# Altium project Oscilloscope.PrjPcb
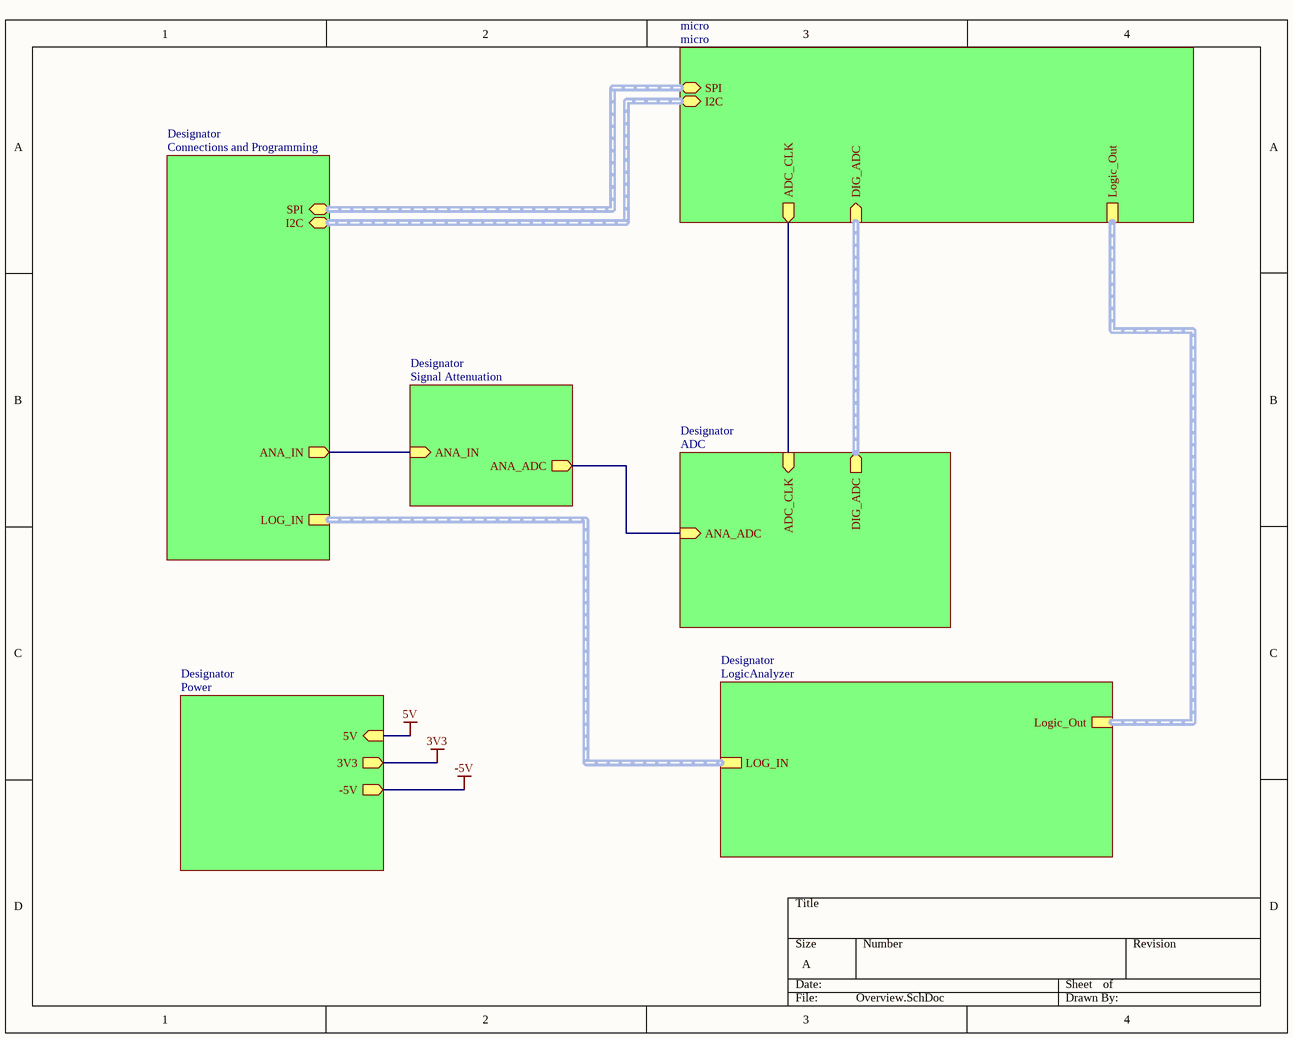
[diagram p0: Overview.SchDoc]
7 sheets, 84 parts. Net scope: hierarchical (ports join the sheet entries above them; power ports are global).
Board file: Oscilloscope.PcbDoc
Sheets:
  Overview.SchDoc
    Designator = Connections and Programming.SchDoc
    micro = micro.SchDoc
    Designator = ADC.SchDoc
    Designator = LogicAnalyzer.SchDoc
    Designator = Power.SchDoc
    Designator = Signal Attenuation.SchDoc

## Sheet Overview.SchDoc
size A

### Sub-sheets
Designator = Connections and Programming: ANA_IN (out), SPI (bidir), I2C (bidir), LOG_IN
Designator = ADC: ADC_CLK (in), DIG_ADC (out), ANA_ADC (in)
Designator = LogicAnalyzer: Logic_Out, LOG_IN
Designator = Power: 5V (in), 3V3 (out), -5V (out)
Designator = Signal Attenuation: ANA_IN (in), ANA_ADC (out)
micro = micro: ADC_CLK (out), DIG_ADC (in), Logic_Out, SPI (bidir), I2C (bidir)

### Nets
ADC_CLK: sheet micro/ADC_CLK, sheet Designator/ADC_CLK
ANA_IN: sheet Designator/ANA_IN, sheet Designator/ANA_IN
ANA_IN_HIGH: sheet Designator/ANA_ADC, sheet Designator/ANA_ADC

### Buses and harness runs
harness sheet Designator/DIG_ADC = sheet micro/DIG_ADC
harness sheet Designator/I2C = sheet micro/I2C
harness sheet Designator/Logic_Out = sheet micro/Logic_Out
harness sheet Designator/SPI = sheet micro/SPI

## Sheet Connections and Programming.SchDoc
size A
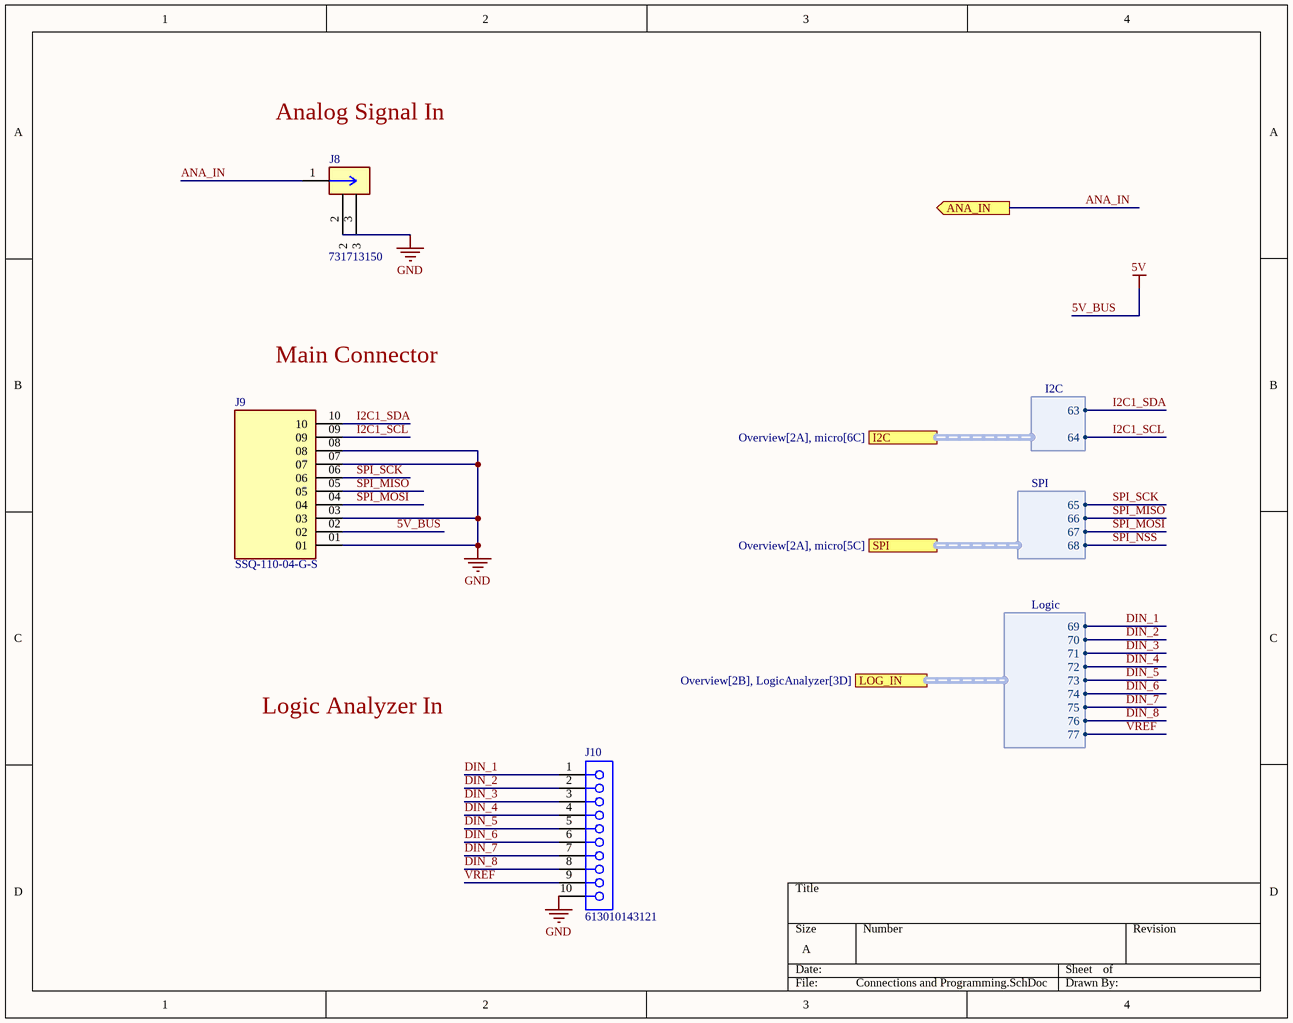
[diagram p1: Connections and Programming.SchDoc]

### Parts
J8  731713150  [CONN_731713150_MOL]
J9  SSQ-110-04-G-S  [SAMTEC_SSQ-110-04-G-S]
J10  613010143121  [613010143121]

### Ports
ANA_IN (out, see Overview[2B], Signal Attenuation[5C]), I2C (harness I2C, see Overview[2A], micro[6C]), LOG_IN (harness Logic, see Overview[2B], LogicAnalyzer[3D]), SPI (harness SPI, see Overview[2A], micro[5C])

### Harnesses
I2C: 63, 64
SPI: 65, 66, 67, 68
Logic: 69, 70, 71, 72, 73, 74, 75, 76, 77

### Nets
5V_BUS: J9.02  [also labelled 5V]
GND: J9.01 J9.03 J9.07 J9.08 J10.10
ANA_IN: J8.1 ; port ANA_IN
DIN_1: J10.1 ; port LOG_IN.69
DIN_2: J10.2 ; port LOG_IN.70
DIN_3: J10.3 ; port LOG_IN.71
DIN_4: J10.4 ; port LOG_IN.72
DIN_5: J10.5 ; port LOG_IN.73
DIN_6: J10.6 ; port LOG_IN.74
DIN_7: J10.7 ; port LOG_IN.75
DIN_8: J10.8 ; port LOG_IN.76
I2C1_SCL: J9.09 ; port I2C.64
I2C1_SDA: J9.10 ; port I2C.63
SPI_MISO: J9.05 ; port SPI.66
SPI_MOSI: J9.04 ; port SPI.67
SPI_SCK: J9.06 ; port SPI.65
VREF: J10.9 ; port LOG_IN.77

Not connected (* = marked no-connect by the designer): J8 2 3

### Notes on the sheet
- Analog Signal In
- Main Connector
- Logic Analyzer In

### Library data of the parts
J8 = CMP-002-00084-4: JACK, BNC, 50OHM, R/A, THT; Connector Type: BNC Coaxial; Body Style: Right Angle J; MP: 73171-3150; MF: Molex
J9 = CMP-039-000000-3: Samtec Connector .1" pitch, long ahh pins
J10 = CMP-1502-01419-3: NexarPartId: 18818161; Operating Supply Voltage: 250V; Contact Resistance: 20mΩ; Gender: Female; Insulation Resistance: 1GΩ; Connector Type: Header, Socket; Insulation: Insulated; Current Rating: 3A; Number of Positions: 10; Pitch: 2.54mm

## Sheet micro.SchDoc
size B
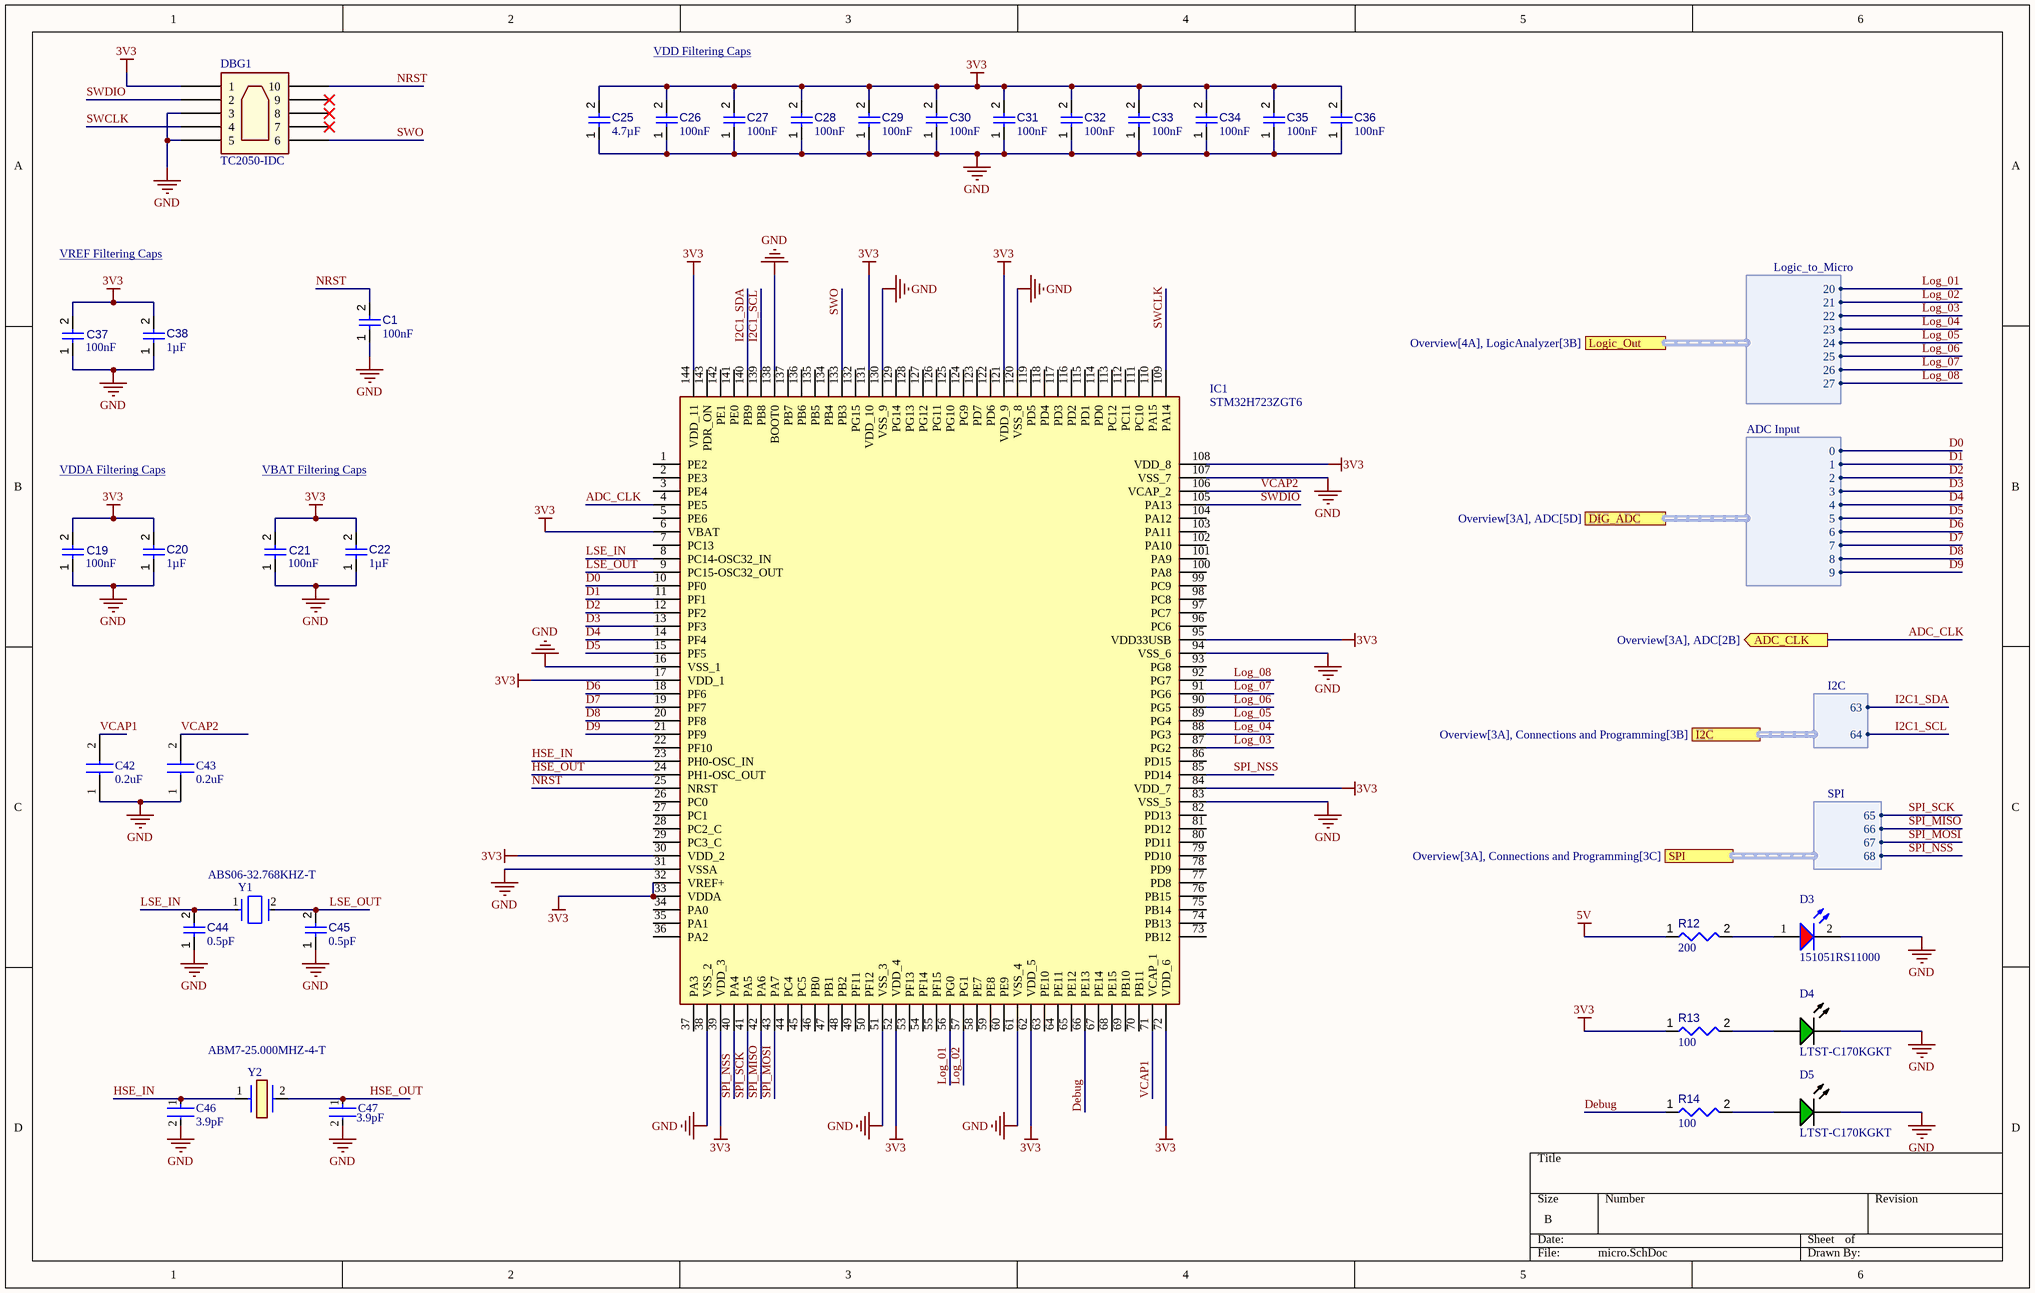
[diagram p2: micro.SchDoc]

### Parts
C1  value 100nF  [CAPC1005X56X25LL10T15]  (hidden comment: Capacitor 0.1 uF +/- 5% 16 V 0402)
C19  value 100nF  [CAPC0402(1005)60_L]  (hidden comment: Capacitor 100nF +/-20% 10V 0402)
C20  value 1µF  [CAPC1608X90X35ML15T15]  (hidden comment: Capacitor 1uF +/- 10% 16V 0603)
C21  value 100nF  [CAPC0402(1005)60_L]  (hidden comment: Capacitor 100nF +/-20% 10V 0402)
C22  value 1µF  [CAPC1608X90X35ML15T15]  (hidden comment: Capacitor 1uF +/- 10% 16V 0603)
C25  value 4.7µF  [CAPC0603(1608)100_L]  (hidden comment: Capacitor 4.7µF +/-20% 10V 0603)
C26  value 100nF  [CAPC0402(1005)60_L]  (hidden comment: Capacitor 100nF +/-20% 10V 0402)
C27  value 100nF  [CAPC0402(1005)60_L]  (hidden comment: Capacitor 100nF +/-20% 10V 0402)
C28  value 100nF  [CAPC0402(1005)60_L]  (hidden comment: Capacitor 100nF +/-20% 10V 0402)
C29  value 100nF  [CAPC0402(1005)60_L]  (hidden comment: Capacitor 100nF +/-20% 10V 0402)
C30  value 100nF  [CAPC0402(1005)60_L]  (hidden comment: Capacitor 100nF +/-20% 10V 0402)
C31  value 100nF  [CAPC0402(1005)60_L]  (hidden comment: Capacitor 100nF +/-20% 10V 0402)
C32  value 100nF  [CAPC0402(1005)60_L]  (hidden comment: Capacitor 100nF +/-20% 10V 0402)
C33  value 100nF  [CAPC0402(1005)60_L]  (hidden comment: Capacitor 100nF +/-20% 10V 0402)
C34  value 100nF  [CAPC0402(1005)60_L]  (hidden comment: Capacitor 100nF +/-20% 10V 0402)
C35  value 100nF  [CAPC0402(1005)60_L]  (hidden comment: Capacitor 100nF +/-20% 10V 0402)
C36  value 100nF  [CAPC0402(1005)60_L]  (hidden comment: Capacitor 100nF +/-20% 10V 0402)
C37  value 100nF  [CAPC0402(1005)60_L]  (hidden comment: Capacitor 100nF +/-20% 10V 0402)
C38  value 1µF  [CAPC1608X90X35ML15T15]  (hidden comment: Capacitor 1uF +/- 10% 16V 0603)
C42  0.2uF  [CAPC3216X94N]
C43  0.2uF  [CAPC3216X94N]
C44  value 0.5pF  [CAPC1005X56X25ML10T15]  (hidden comment: Capacitor 0.5 pF +/- 0.1pF 25 V 0402)
C45  value 0.5pF  [CAPC1005X56X25ML10T15]  (hidden comment: Capacitor 0.5 pF +/- 0.1pF 25 V 0402)
C46  3.9pF  [FP-GJM155-0_05-IPC_C]
C47  3.9pF  [FP-GJM155-0_05-IPC_C]
D3  151051RS11000  [WL-TMRC_D5.9H8.7]
D4  LTST-C170KGKT  [LTST-LTST-C170KGKT-2_V]
D5  LTST-C170KGKT  [LTST-LTST-C170KGKT-2_V]
DBG1  TC2050-IDC  [TC2050-IDC-Footprint-1]
IC1  STM32H723ZGT6  [QFP50P2200X2200X160-144N]
R12  value 200  [RESC0402(1005)_L]  (hidden comment: 200R2J)
R13  value 100  [RESC0402(1005)_L]  (hidden comment: 100R2F)
R14  value 100  [RESC0402(1005)_L]  (hidden comment: 100R2F)
Y1  ABS06-32.768KHZ-T  [FP-ABS06-MFG]
Y2  ABM7-25.000MHZ-4-T  [ABM7]

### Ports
ADC_CLK (out, see Overview[3A], ADC[2B]), DIG_ADC (harness ADC Input, see Overview[3A], ADC[5D]), I2C (harness I2C, see Overview[3A], Connections and Programming[3B]), Logic_Out (harness Logic_to_Micro, see Overview[4A], LogicAnalyzer[3B]), SPI (harness SPI, see Overview[3A], Connections and Programming[3C])

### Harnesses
ADC Input: 0, 1, 2, 3, 4, 5, 6, 7, 8, 9
Logic_to_Micro: 20, 21, 22, 23, 24, 25, 26, 27
I2C: 63, 64
SPI: 65, 66, 67, 68

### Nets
3V3: C19.2 C20.2 C21.2 C22.2 C25.2 C26.2 C27.2 C28.2 C29.2 C30.2 C31.2 C32.2 C33.2 C34.2 C35.2 C36.2 C37.2 C38.2 DBG1.1 IC1.6(VBAT) IC1.17(VDD_1) IC1.30(VDD_2) IC1.32(VREF+) IC1.33(VDDA) IC1.39(VDD_3) IC1.52(VDD_4) IC1.62(VDD_5) IC1.72(VDD_6) IC1.84(VDD_7) IC1.95(VDD33USB) IC1.108(VDD_8) IC1.121(VDD_9) IC1.131(VDD_10) IC1.144(VDD_11) R13.1
5V: R12.1  [project net 5V_BUS]
GND: C1.1 C19.1 C20.1 C21.1 C22.1 C25.1 C26.1 C27.1 C28.1 C29.1 C30.1 C31.1 C32.1 C33.1 C34.1 C35.1 C36.1 C37.1 C38.1 C42.1(C1) C43.1(C1) C44.1 C45.1 C46.2 C47.2 D3.2(K) D4.1(K) D5.1(K) DBG1.3 DBG1.5 IC1.16(VSS_1) IC1.31(VSSA) IC1.38(VSS_2) IC1.51(VSS_3) IC1.61(VSS_4) IC1.83(VSS_5) IC1.94(VSS_6) IC1.107(VSS_7) IC1.120(VSS_8) IC1.130(VSS_9) IC1.138(BOOT0)
ADC_CLK: IC1.4(PE5) ; port ADC_CLK
D0: IC1.10(PF0) ; port DIG_ADC.0
D1: IC1.11(PF1) ; port DIG_ADC.1
D2: IC1.12(PF2) ; port DIG_ADC.2
D3: IC1.13(PF3) ; port DIG_ADC.3
D4: IC1.14(PF4) ; port DIG_ADC.4
D5: IC1.15(PF5) ; port DIG_ADC.5
D6: IC1.18(PF6) ; port DIG_ADC.6
D7: IC1.19(PF7) ; port DIG_ADC.7
D8: IC1.20(PF8) ; port DIG_ADC.8
D9: IC1.21(PF9) ; port DIG_ADC.9
Debug: IC1.66(PE13) R14.1
HSE_IN: C46.1 IC1.23(PH0-OSC_IN) Y2.1
HSE_OUT: C47.1 IC1.24(PH1-OSC_OUT) Y2.2
I2C1_SCL: IC1.139(PB8) ; port I2C.64
I2C1_SDA: IC1.140(PB9) ; port I2C.63
Log_01: IC1.56(PG0) ; port Logic_Out.20
Log_02: IC1.57(PG1) ; port Logic_Out.21
Log_03: IC1.87(PG2) ; port Logic_Out.22
Log_04: IC1.88(PG3) ; port Logic_Out.23
Log_05: IC1.89(PG4) ; port Logic_Out.24
Log_06: IC1.90(PG5) ; port Logic_Out.25
Log_07: IC1.91(PG6) ; port Logic_Out.26
Log_08: IC1.92(PG7) ; port Logic_Out.27
LSE_IN: C44.2 IC1.8(PC14-OSC32_IN) Y1.1
LSE_OUT: C45.2 IC1.9(PC15-OSC32_OUT) Y1.2
NRST: C1.2 DBG1.10 IC1.25(NRST)
SPI_MISO: IC1.42(PA6) ; port SPI.66
SPI_MOSI: IC1.43(PA7) ; port SPI.67
SPI_NSS: IC1.40(PA4) IC1.85(PD14) ; port SPI.68
SPI_SCK: IC1.41(PA5) ; port SPI.65
SWCLK: DBG1.4 IC1.109(PA14)
SWDIO: DBG1.2 IC1.105(PA13)
SWO: DBG1.6 IC1.133(PB3)
VCAP1: C42.2(C2) IC1.71(VCAP_1)
VCAP2: C43.2(C2) IC1.106(VCAP_2)
NetD3_1: D3.1(A) R12.2
NetD4_2: D4.2(A) R13.2
NetD5_2: D5.2(A) R14.2

Not connected (* = marked no-connect by the designer): DBG1 7* 8* 9*; IC1 1(PE2) 2(PE3) 3(PE4) 5(PE6) 7(PC13) 22(PF10) 26(PC0) 27(PC1) 28(PC2_C) 29(PC3_C) 34(PA0) 35(PA1) 36(PA2) 37(PA3) 44(PC4) 45(PC5) 46(PB0) 47(PB1) 48(PB2) 49(PF11) 50(PF12) 53(PF13) 54(PF14) 55(PF15) 58(PE7) 59(PE8) 60(PE9) 63(PE10) 64(PE11) 65(PE12) 67(PE14) 68(PE15) 69(PB10) 70(PB11) 73(PB12) 74(PB13) 75(PB14) 76(PB15) 77(PD8) 78(PD9) 79(PD10) 80(PD11) 81(PD12) 82(PD13) 86(PD15) 93(PG8) 96(PC6) 97(PC7) 98(PC8) 99(PC9) 100(PA8) 101(PA9) 102(PA10) 103(PA11) 104(PA12) 110(PA15) 111(PC10) 112(PC11) 113(PC12) 114(PD0) 115(PD1) 116(PD2) 117(PD3) 118(PD4) 119(PD5) 122(PD6) 123(PD7) 124(PG9) 125(PG10) 126(PG11) 127(PG12) 128(PG13) 129(PG14) 132(PG15) 134(PB4) 135(PB5) 136(PB6) 137(PB7) 141(PE0) 142(PE1) 143(PDR_ON)

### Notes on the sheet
- VDD Filtering Caps
- VREF Filtering Caps
- VDDA Filtering Caps
- VBAT Filtering Caps

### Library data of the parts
C1 = CMP-001-00001-6: Chip Capacitor, 0.1 uF, +/- 5%, 16 V, 0402 (1005 Metric); Capacitor Type: Ceramic; Voltage Rating: 16V
C19 C21 C26-C37 = CMP-001-00061-3: Chip Capacitor, 100nF +/-20%, 10V, 0402, Thickness 0.6 mm; Tolerance: 20%
C20 C22 C38 = CMP-001-00004-6: Chip Capacitor, 1 uF, +/- 10%, 16 V, 0603 (1608 Metric); Capacitor Type: Ceramic
C25 = CMP-001-00076-4: Chip Capacitor, 4.7µF +/-20%, 10V, 0603, Thickness 1 mm; Tolerance: 10%
C42 C43 = 12063C204KAT4A: Capacitor; Manufacturer_Name: Kyocera AVX
C44 C45 = CMP-001-00002-6: Chip Capacitor, 0.5 pF, +/- 0.1pF, 25 V, 0402 (1005 Metric); Voltage Rating: 25V; Tolerance: 20%; Capacitor Type: Ceramic
C46 C47 = CMP-2008-03853-2: Multi-Layer Ceramic Capacitor 3.9pF C0G  ±0.25pF 0402 Paper T/R; Voltage Rating (DC): 50V
D3 = CMP-007-00039-1: WL-TMRC Red Color Diffused 5 mm Round Through Hole LED; Forward Voltage: 2.1V; Forward Current: 100mA
D4 D5 = CMP-2000-06620-1: Ultra Bright AlInGaP Chip LED, 75 mW, -55 to 85 degC, 2-Pin SMD (0805), RoHS, Tape and Reel; Manufacturer: Lite-On; Forward Current: 30mA; Power Dissipation Max: 75mW; Emitting Color: YellowGreen; Type: Uni-Color; Forward Voltage: 2.4V; Dominant Wave Length: 571nm; Test Current (It): 20mA; Product Length (mm): 2mm; Peak Wavelength: 574nm; Power Dissipation: 75W; Product Depth (mm): 1.25mm; DELETED: Compliant; High Brightness: Yes; Product Height (mm): 1.1mm; Luminous Intensity: 35mcd; Shape Type: Rectangular; Chip Material: AlGaInP; Viewing Angle: 130deg; Number of  Elements: 1; Reverse Voltage: 5V; Rad Hardened: No
DBG1 = CMP-002-00071-4: CBL PLUG-OF-NAILS 10-PIN W/LEGS
IC1 = STM32H723ZGT6: Integrated Circuit; Manufacturer_Name: STMicroelectronics
R12 = CMP-009-00079-2: 200R 0.063W 5% 0402 (1005 Metric)  SMD; Power: 63mW
R13 R14 = CMP-009-00065-2: 100R 0.063W 1% 0402 (1005 Metric)  SMD; Power: 63mW
Y1 = CMP-2000-05035-2: Crystal 32.768kHz ±20ppm (Tol) 12.5pF FUND 90kΩ 2-Pin Mini-CSMD T/R; Insulation Resistance: 500MR; ESR (Equivalent Series Resistance): 90kR
Y2 = ABM7-25.000MHZ-4-T: Crystal or Oscillator; Manufacturer_Name: ABRACON

## Sheet ADC.SchDoc
size B
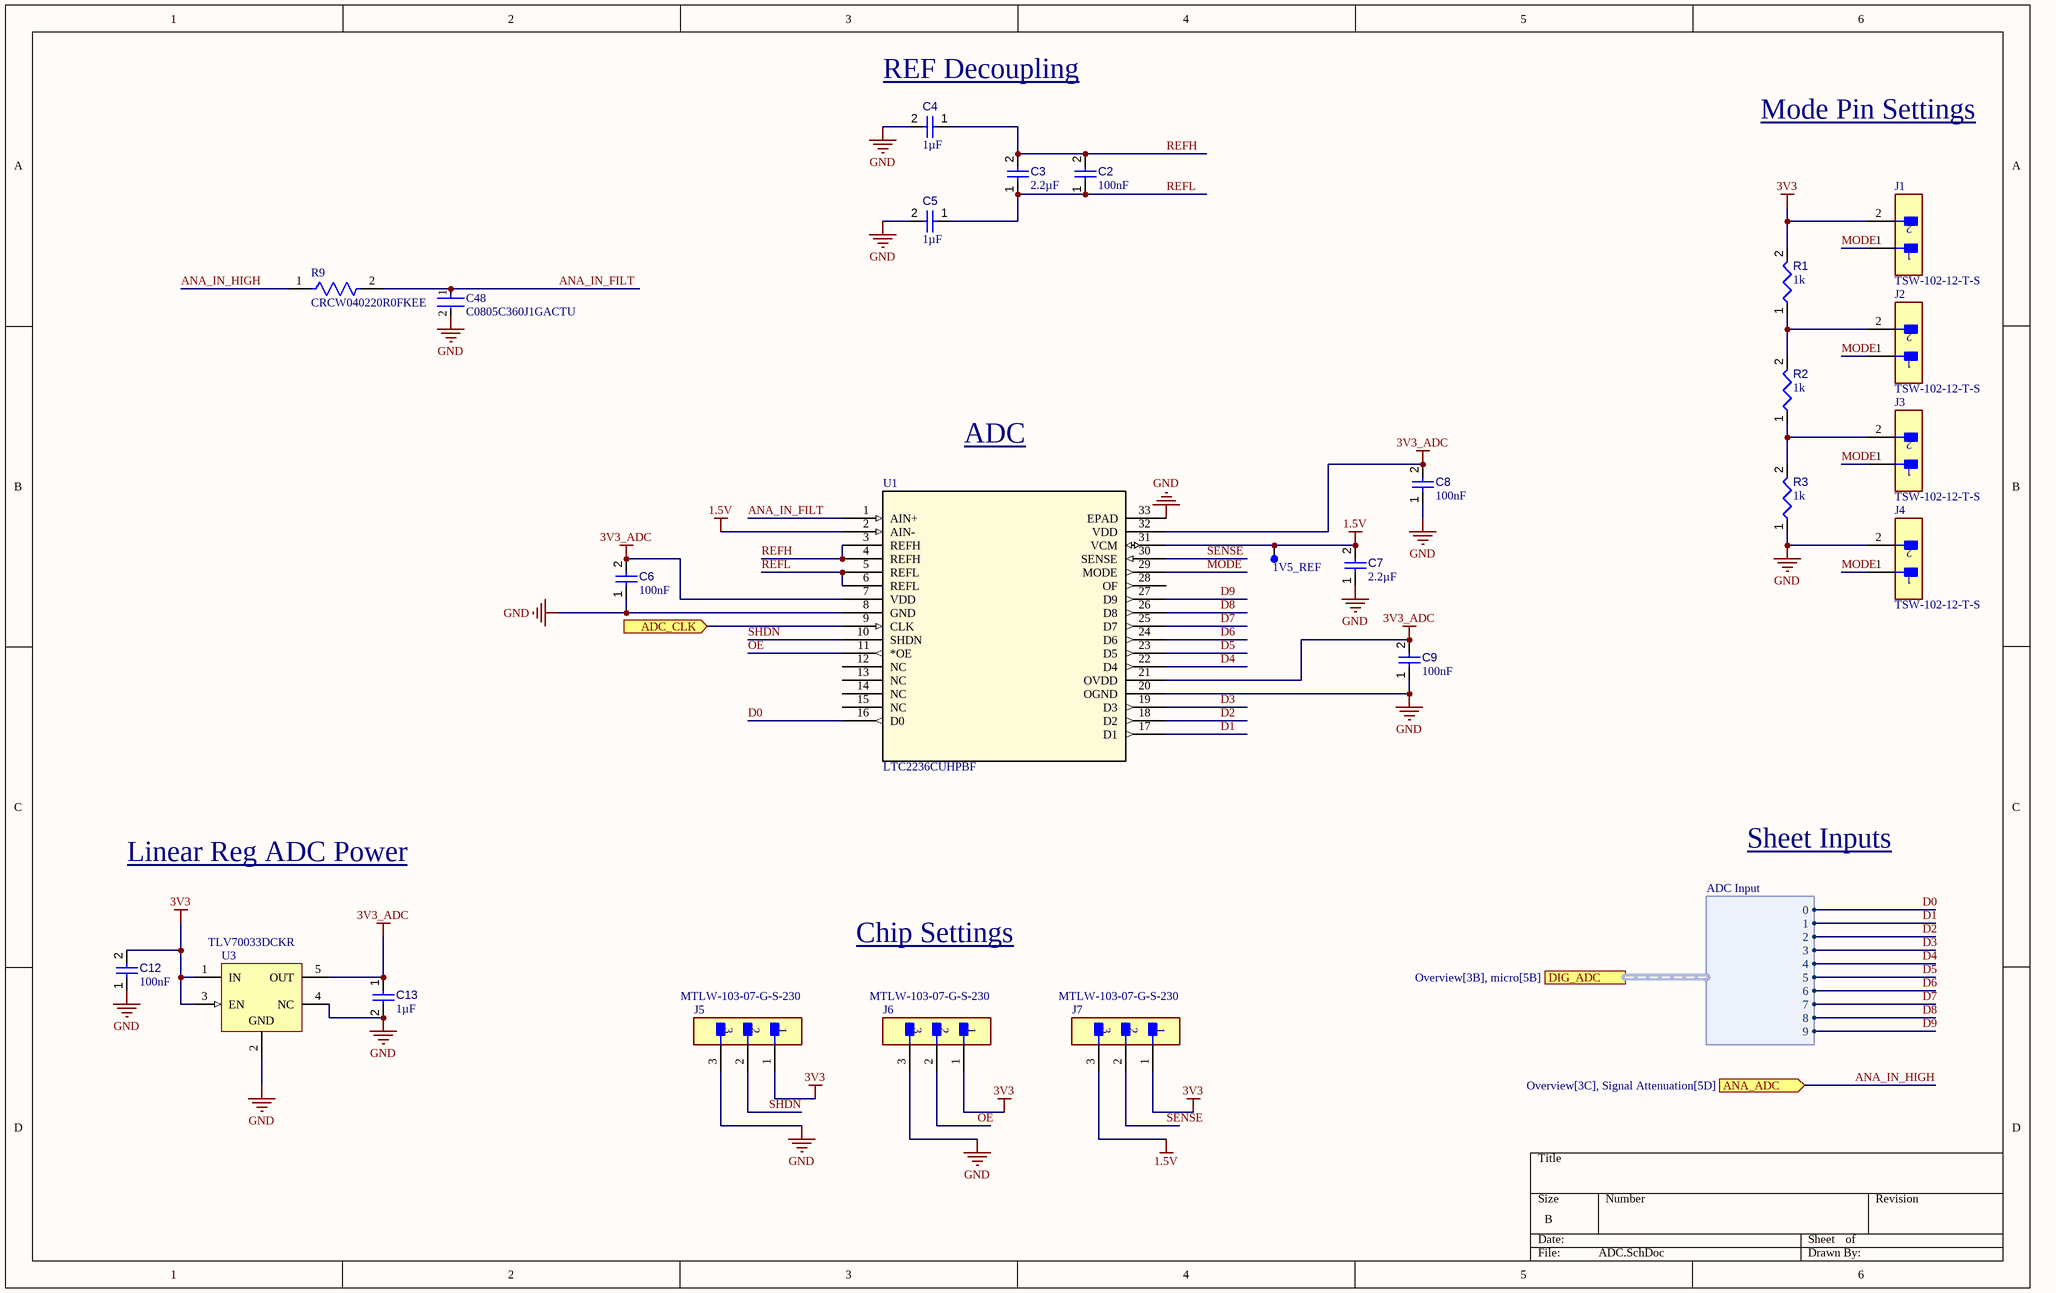
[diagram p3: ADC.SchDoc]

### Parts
1V5_REF  TESTPAD  [TESTPAD-Footprint-1]  (value not drawn)
C2  value 100nF  [CAPC1005X56X25LL10T15]  (hidden comment: Capacitor 0.1 uF +/- 5% 16 V 0402)
C3  value 2.2µF  [CAPC0402(1005)60_L]  (hidden comment: Capacitor 2,2µF +/-20% 10V 0402)
C4  value 1µF  [CAPC0402(1005)60_L]  (hidden comment: Capacitor 1µF +/-20% 10V 0402)
C5  value 1µF  [CAPC0402(1005)60_L]  (hidden comment: Capacitor 1µF +/-20% 10V 0402)
C6  value 100nF  [CAPC1005X56X25LL10T15]  (hidden comment: Capacitor 0.1 uF +/- 5% 16 V 0402)
C7  value 2.2µF  [CAPC0402(1005)60_L]  (hidden comment: Capacitor 2,2µF +/-20% 10V 0402)
C8  value 100nF  [CAPC1005X56X25LL10T15]  (hidden comment: Capacitor 0.1 uF +/- 5% 16 V 0402)
C9  value 100nF  [CAPC1005X56X25LL10T15]  (hidden comment: Capacitor 0.1 uF +/- 5% 16 V 0402)
C12  value 100nF  [CAPC1005X56X25LL10T15]  (hidden comment: Capacitor 0.1 uF +/- 5% 16 V 0402)
C13  value 1µF  [CAPC0402(1005)60_L]  (hidden comment: Capacitor 1µF +/-20% 10V 0402)
C48  C0805C360J1GACTU  [FP-C0805C-DN-MFG]
J1  TSW-102-12-T-S  [FP-TSW-102-12-T-S-MFG]
J2  TSW-102-12-T-S  [FP-TSW-102-12-T-S-MFG]
J3  TSW-102-12-T-S  [FP-TSW-102-12-T-S-MFG]
J4  TSW-102-12-T-S  [FP-TSW-102-12-T-S-MFG]
J5  MTLW-103-07-G-S-230  [FP-MTLW-103-07-G-S-230-MFG]
J6  MTLW-103-07-G-S-230  [FP-MTLW-103-07-G-S-230-MFG]
J7  MTLW-103-07-G-S-230  [FP-MTLW-103-07-G-S-230-MFG]
R1  value 1k  [RESC1608X55X25ML10T15]  (hidden comment: Resistor 1k +/-1% 0603 100 mW)
R2  value 1k  [RESC1608X55X25ML10T15]  (hidden comment: Resistor 1k +/-1% 0603 100 mW)
R3  value 1k  [RESC1608X55X25ML10T15]  (hidden comment: Resistor 1k +/-1% 0603 100 mW)
R9  CRCW040220R0FKEE  [FP-CRCW0402-e3-IPC_C]
U1  LTC2236CUHPBF  [QFN-32_UH_LIT]
U3  TLV70033DCKR  [DCK0005A_M]

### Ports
ADC_CLK (in, see Overview[3B], micro[6B]), ANA_ADC (in, see Overview[3C], Signal Attenuation[5D]), DIG_ADC (harness ADC Input, see Overview[3B], micro[5B])

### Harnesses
ADC Input: 0, 1, 2, 3, 4, 5, 6, 7, 8, 9

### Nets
1.5V: 1V5_REF.PAD C7.2 J7.3 U1.2(AIN-) U1.31(VCM)
3V3: C12.2 J1.2 J5.1 J6.1 J7.1 R1.2 U3.1(IN) U3.3(EN)
3V3_ADC: C6.2 C8.2 C9.2 C13.1 U1.7(VDD) U1.21(OVDD) U1.32(VDD) U3.5(OUT)
GND: C4.2 C5.2 C6.1 C7.1 C8.1 C9.1 C12.1 C13.2 C48.2 J4.2 J5.3 J6.3 R3.1 U1.8(GND) U1.20(OGND) U1.33(EPAD) U3.2(GND) U3.4(NC)
ADC_CLK: U1.9(CLK) ; port ADC_CLK
ANA_IN_FILT: C48.1 R9.2 U1.1(AIN+)
ANA_IN_HIGH: R9.1 ; port ANA_ADC
D0: U1.16(D0) ; port DIG_ADC.0
D1: U1.17(D1) ; port DIG_ADC.1
D2: U1.18(D2) ; port DIG_ADC.2
D3: U1.19(D3) ; port DIG_ADC.3
D4: U1.22(D4) ; port DIG_ADC.4
D5: U1.23(D5) ; port DIG_ADC.5
D6: U1.24(D6) ; port DIG_ADC.6
D7: U1.25(D7) ; port DIG_ADC.7
D8: U1.26(D8) ; port DIG_ADC.8
D9: U1.27(D9) ; port DIG_ADC.9
MODE: J1.1 J2.1 J3.1 J4.1 U1.29(MODE)
OE: J6.2 U1.11(*OE)
REFH: C2.2 C3.2 C4.1 U1.3(REFH) U1.4(REFH)
REFL: C2.1 C3.1 C5.1 U1.5(REFL) U1.6(REFL)
SENSE: J7.2 U1.30(SENSE)
SHDN: J5.2 U1.10(SHDN)
NetJ2_2: J2.2 R1.1 R2.2
NetJ3_2: J3.2 R2.1 R3.2

Not connected (* = marked no-connect by the designer): U1 12(NC) 13(NC) 14(NC) 15(NC) 28(OF)

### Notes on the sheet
- (near C4) REF Decoupling
- Mode Pin Settings
- ADC
- Linear Reg ADC Power
- Sheet Inputs
- Chip Settings

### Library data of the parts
1V5_REF = CMP-002-00073-1: PCB TESTPAD
C2 C6 C8 C9 C12 = CMP-001-00001-6: as C1 on sheet micro
C3 C7 = CMP-001-00056-4: Chip Capacitor, 2,2µF +/-20%, 10V, 0402, Thickness 0.6 mm; Tolerance: 10%
C4 C5 C13 = CMP-001-00063-3: Chip Capacitor, 1µF +/-20%, 10V, 0402, Thickness 0.6 mm; Tolerance: 10%
C48 = CMP-1036-01479-3: Capacitor, Ceramic, 36pF, 100VDC, 5-% Tol, 5+% Tol, C0G-TC Code, -30, 30ppm-TC; Manufacturer: KEMET; Temperature Characteristic: C0G; Description: C0805 36 pF C0G 30ppm/°C 5.00% 100 V; Tolerance: 0.05; Voltage Rating: 100 V; Temperature Coefficient: 30ppm/°C
J1-J4 = CMP-02766-001444-1: CONN HEADER VERT 2POS 2.54MM; Gender: Male; Number of Contacts: 2
J5-J7 = CMP-02766-001679-1: CONN HEADER VERT 3POS 2.54MM; Max Current Rating: 3A; Number of Contacts: 3; Gender: Male
R1-R3 = CMP-009-00014-5: Chip Resistor, 1 KOhm, +/-1%, 0.1 W, -55 to 155 degC, 0603 (1608 Metric); Voltage Rating: 50V; Power: 100mW; Tolerance: 1%
R9 = CMP-02407-010876-1: RES Thick Film, 20Ω, 1%, 0.063W, 100ppm/°C, 0402; Max Power Dissipation: 63mW; Resistance: 20R
U1 = CMP-027-000001-1: 10-Bit, 25Msps Low Noise 3V ADCs; Manufacturer_Name: Analog Devices Inc; Manufacturer_Part_Number: LTC2236CUH#PBF
U3 = CMP-0394-00820-2: Single Output LDO, 200 mA, Fixed 3.3 V Output, 2 to 5.5 V Input, with Low IQ, 5-pin SC70 (DCK), -40 to 125 degC, Green (RoHS & no Sb/Br); Manufacturer: Texas Instruments; SubFamily: Single Channel LDO; Fixed Output Options(V): 3.3; Vin(Max)(V): 5.5; Vin(Min)(V): 2; Vdo(Typ)(mV): 175; Iq(Typ)(mA): 0.03; Iout(Max)(A): 0.2

## Sheet LogicAnalyzer.SchDoc
size B
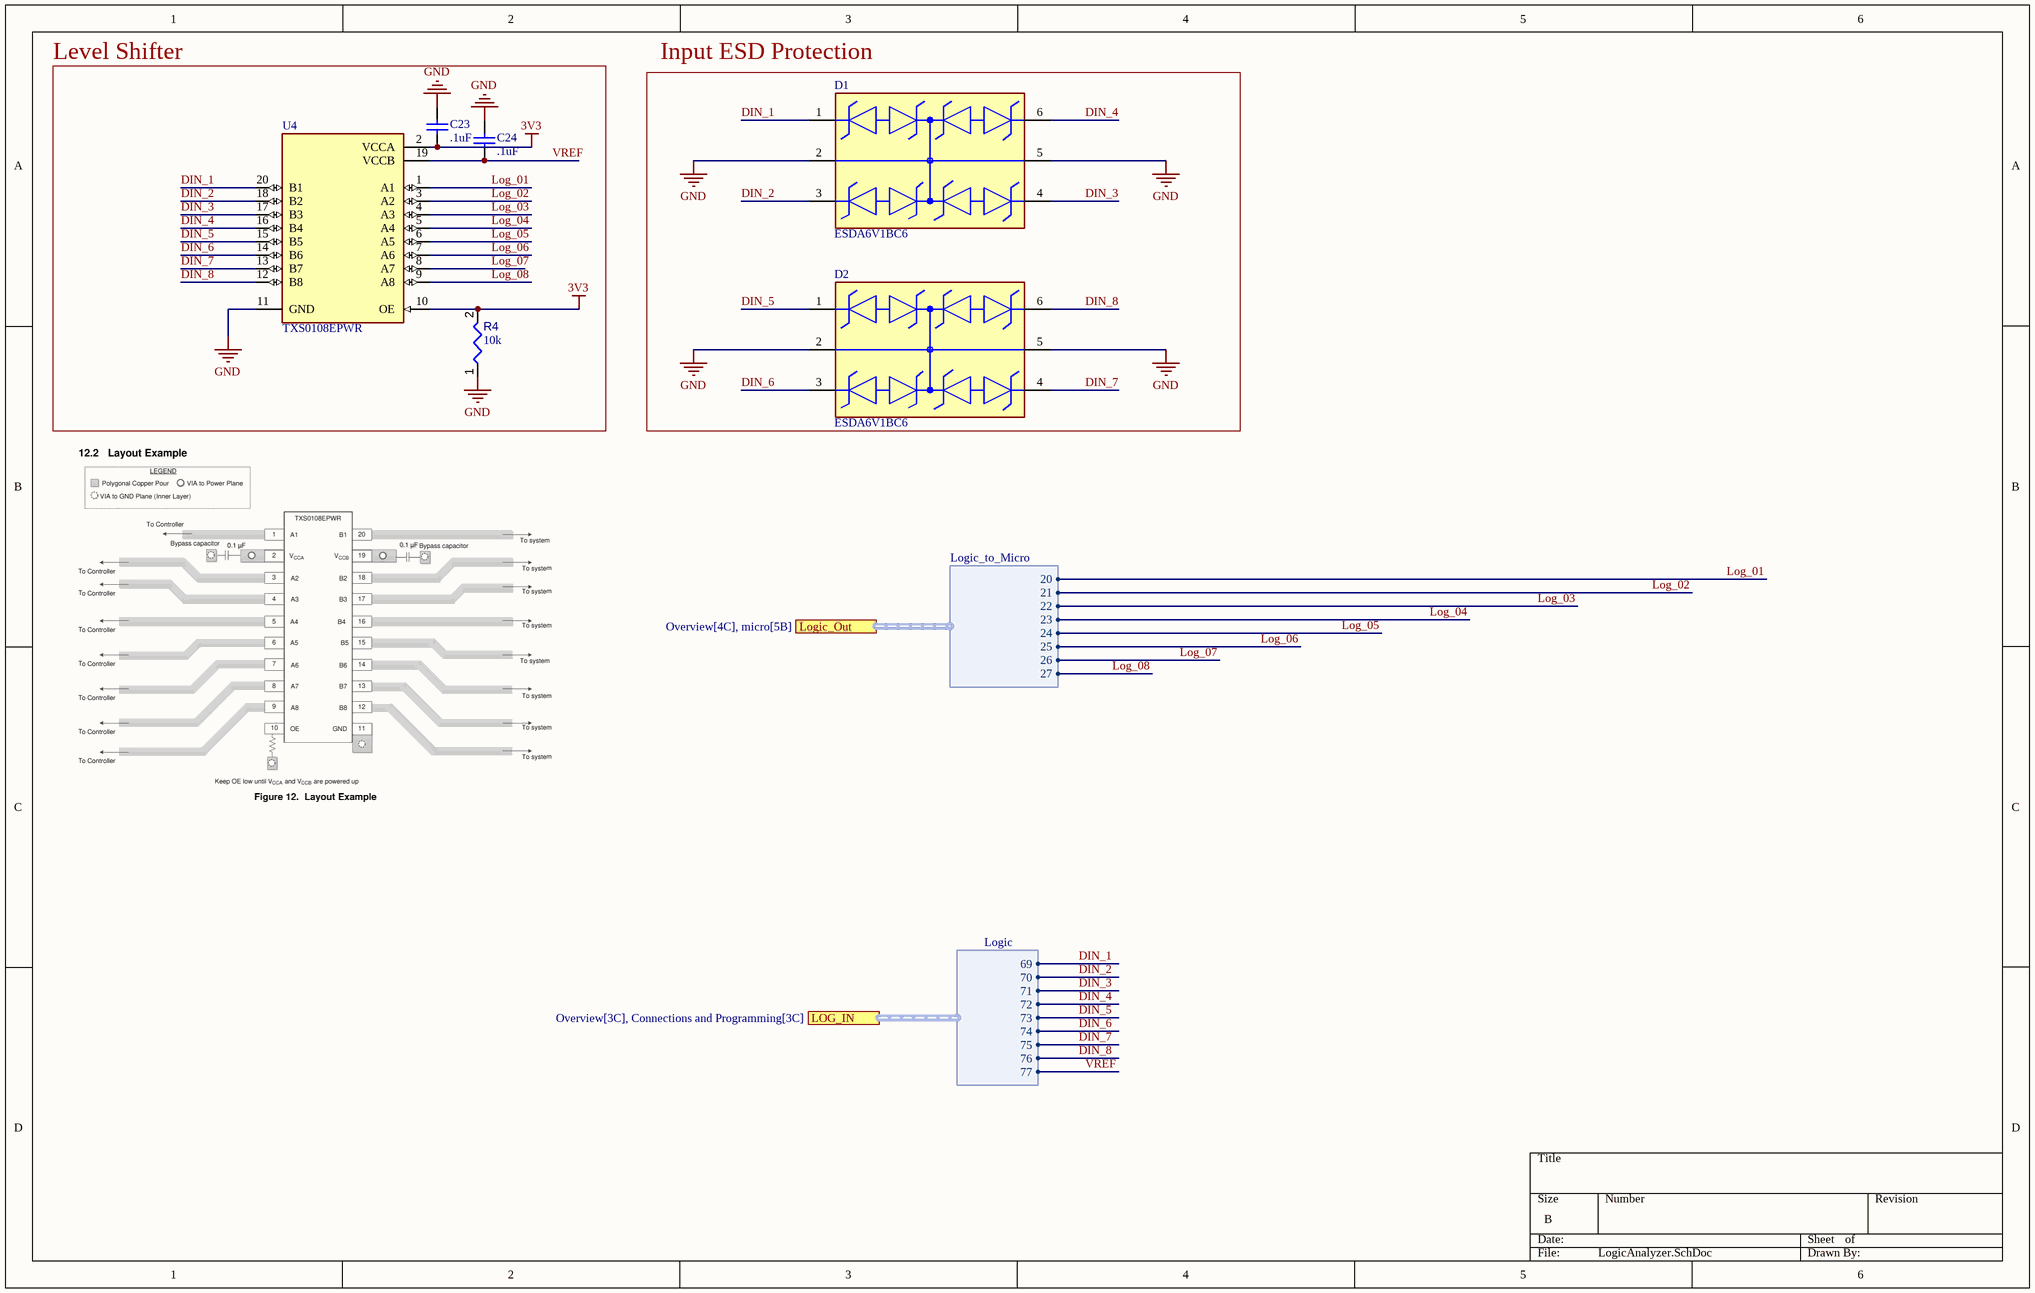
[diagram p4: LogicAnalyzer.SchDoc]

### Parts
C23  .1uF  [CAPC1608X90X35NL15T15]
C24  .1uF  [CAPC1608X90X35NL15T15]
D1  ESDA6V1BC6  [FP-SOT23-6L-MFG]
D2  ESDA6V1BC6  [FP-SOT23-6L-MFG]
R4  value 10k  [RESC0402(1005)_L]  (hidden comment: Resistor 10K  +/-1 % 0402 63 mW)
U4  TXS0108EPWR  [FP-PW0020A-IPC_A]

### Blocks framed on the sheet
Level Shifter: C23 C24 R4 U4
Input ESD Protection: D1 D2

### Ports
LOG_IN (harness Logic, see Overview[3C], Connections and Programming[3C]), Logic_Out (harness Logic_to_Micro, see Overview[4C], micro[5B])

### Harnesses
Logic_to_Micro: 20, 21, 22, 23, 24, 25, 26, 27
Logic: 69, 70, 71, 72, 73, 74, 75, 76, 77

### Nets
3V3: C23.2 R4.2 U4.2(VCCA) U4.10(OE)
GND: C23.1 C24.1 D1.2 D1.5 D2.2 D2.5 R4.1 U4.11(GND)
DIN_1: D1.1 U4.20(B1) ; port LOG_IN.69
DIN_2: D1.3 U4.18(B2) ; port LOG_IN.70
DIN_3: D1.4 U4.17(B3) ; port LOG_IN.71
DIN_4: D1.6 U4.16(B4) ; port LOG_IN.72
DIN_5: D2.1 U4.15(B5) ; port LOG_IN.73
DIN_6: D2.3 U4.14(B6) ; port LOG_IN.74
DIN_7: D2.4 U4.13(B7) ; port LOG_IN.75
DIN_8: D2.6 U4.12(B8) ; port LOG_IN.76
Log_01: U4.1(A1) ; port Logic_Out.20
Log_02: U4.3(A2) ; port Logic_Out.21
Log_03: U4.4(A3) ; port Logic_Out.22
Log_04: U4.5(A4) ; port Logic_Out.23
Log_05: U4.6(A5) ; port Logic_Out.24
Log_06: U4.7(A6) ; port Logic_Out.25
Log_07: U4.8(A7) ; port Logic_Out.26
Log_08: U4.9(A8) ; port Logic_Out.27
VREF: C24.2 U4.19(VCCB) ; port LOG_IN.77

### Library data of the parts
C23 C24 = CMP-2006-02299-1: C0603C104K4RAC7013; Manufacturer: Kemet
D1 D2 = CMP-12225-000005-1: TVS DIODE 5V SOT23-6; Manufacturer: STMicroelectronics; Direction: Bidirectional; Capacitance: 20pF; Standoff Height: 0mm; Number Of Channels: 4; Peak Pulse Power: 80W; Max Junction Temp: +150°C; Breakdown Voltage: 6.1V; Peak Pulse Current: 3A; Value: 20pF
R4 = CMP-009-00149-3: Chip Resistor, 10 kOhms, +/-1 %, 63 mW, -55 to 125 degC, 0402; Power: 63mW; Tolerance: 1%
U4 = CMP-016-00012-1: Eight-bit bidirectional voltage-level shifter for open-drain and push-pull applications 20-TSSOP -40 to 85; Min Supply Voltage: 1.4V; Nominal Supply Current: 3µA; Max Supply Voltage: 5.5V

## Sheet Power.SchDoc
size A
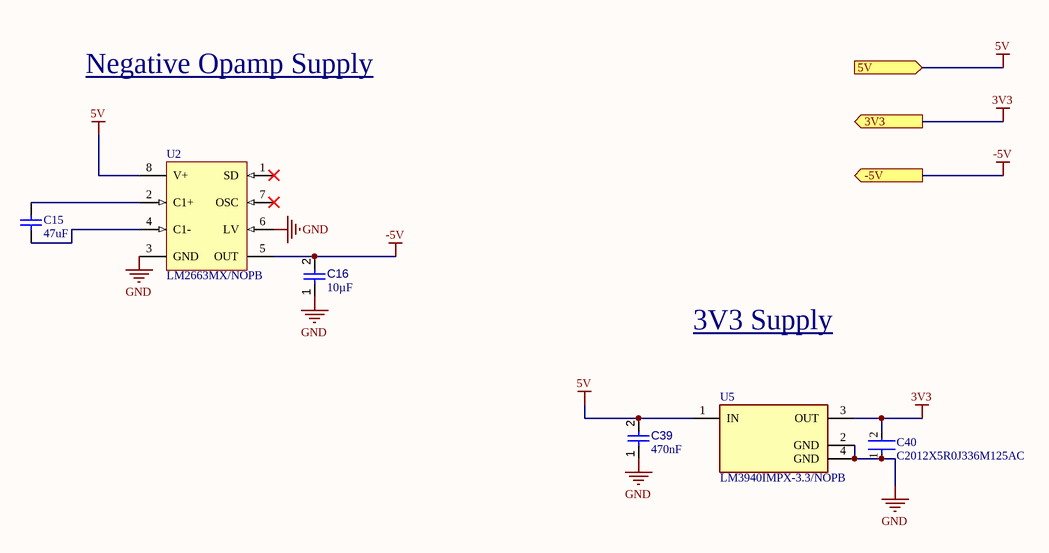
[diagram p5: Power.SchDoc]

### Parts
C15  47uF  [CAPC1206(3216)190_N]
C16  value 10µF  [CAPC0603(1608)100_L]  (hidden comment: Capacitor 10µF +/-20% 10V 0603)
C39  value 470nF  [CAPC0402(1005)60_L]  (hidden comment: Capacitor 470nF +/-40% 10V 0402)
C40  C2012X5R0J336M125AC  [FP-C2012-125-0_2-IPC_A]
U2  LM2663MX/NOPB  [D0008A_M]
U5  LM3940IMPX-3.3/NOPB  [FP-DCY0004A-MFG]

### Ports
3V3 (out), 5V (in), -5V (out)

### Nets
3V3: C40.2 U5.3(OUT) ; port 3V3
5V: C39.2 U2.8(V+) U5.1(IN) ; port 5V  [project net 5V_BUS]
-5V: C16.2 U2.5(OUT) ; port -5V
GND: C16.1 C39.1 C40.1 U2.3(GND) U2.6(LV) U5.2(GND) U5.4(GND)
NetC15_1: C15.1 U2.4(C1-)
NetC15_2: C15.2 U2.2(C1+)

Not connected (* = marked no-connect by the designer): U2 1(SD)* 7(OSC)*

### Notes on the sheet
- Negative Opamp Supply
- 3V3 Supply

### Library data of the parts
C15 = CMP-1037-05002-1: CAP 47uF 10V ±20% 1206 (3216 Metric) Thickness 1.9mm SMD; Case-Metric: 3216; Case-EIA: 1206; Tolerance: Â±20%
C16 = CMP-001-00075-4: Chip Capacitor, 10µF +/-20%, 10V, 0603, Thickness 1 mm; Tolerance: 10%
C39 = CMP-001-00060-4: Chip Capacitor, 470nF +/-40%, 10V, 0402, Thickness 0.6 mm; Tolerance: 20%
C40 = CMP-08246-003796-1: Multilayer Ceramic Capacitors 33μF ±20% 6.3V X5R SMD 0805; Capacitance: 33uF
U2 = CMP-0065-00039-3: Switched Capacitor Voltage Converter, 8-pin Narrow SOIC, Pb-Free; Manufacturer: Texas Instruments; PowerWise: N; PackageTopMarking: NSZXTT*LM26*63M; CompType: Switch Caps
U5 = CMP-04917-000180-1: IC REG LINEAR 3.3V 1A SOT223-4; Polarity: Positive; Dropout Voltage: 500mV; Number of Regulators: 1; Min Input Voltage: 4.5V; Quiescent Current: 15mA; Output Type: Fixed; Max Input Voltage: 7.5V

## Sheet Signal Attenuation.SchDoc
size B
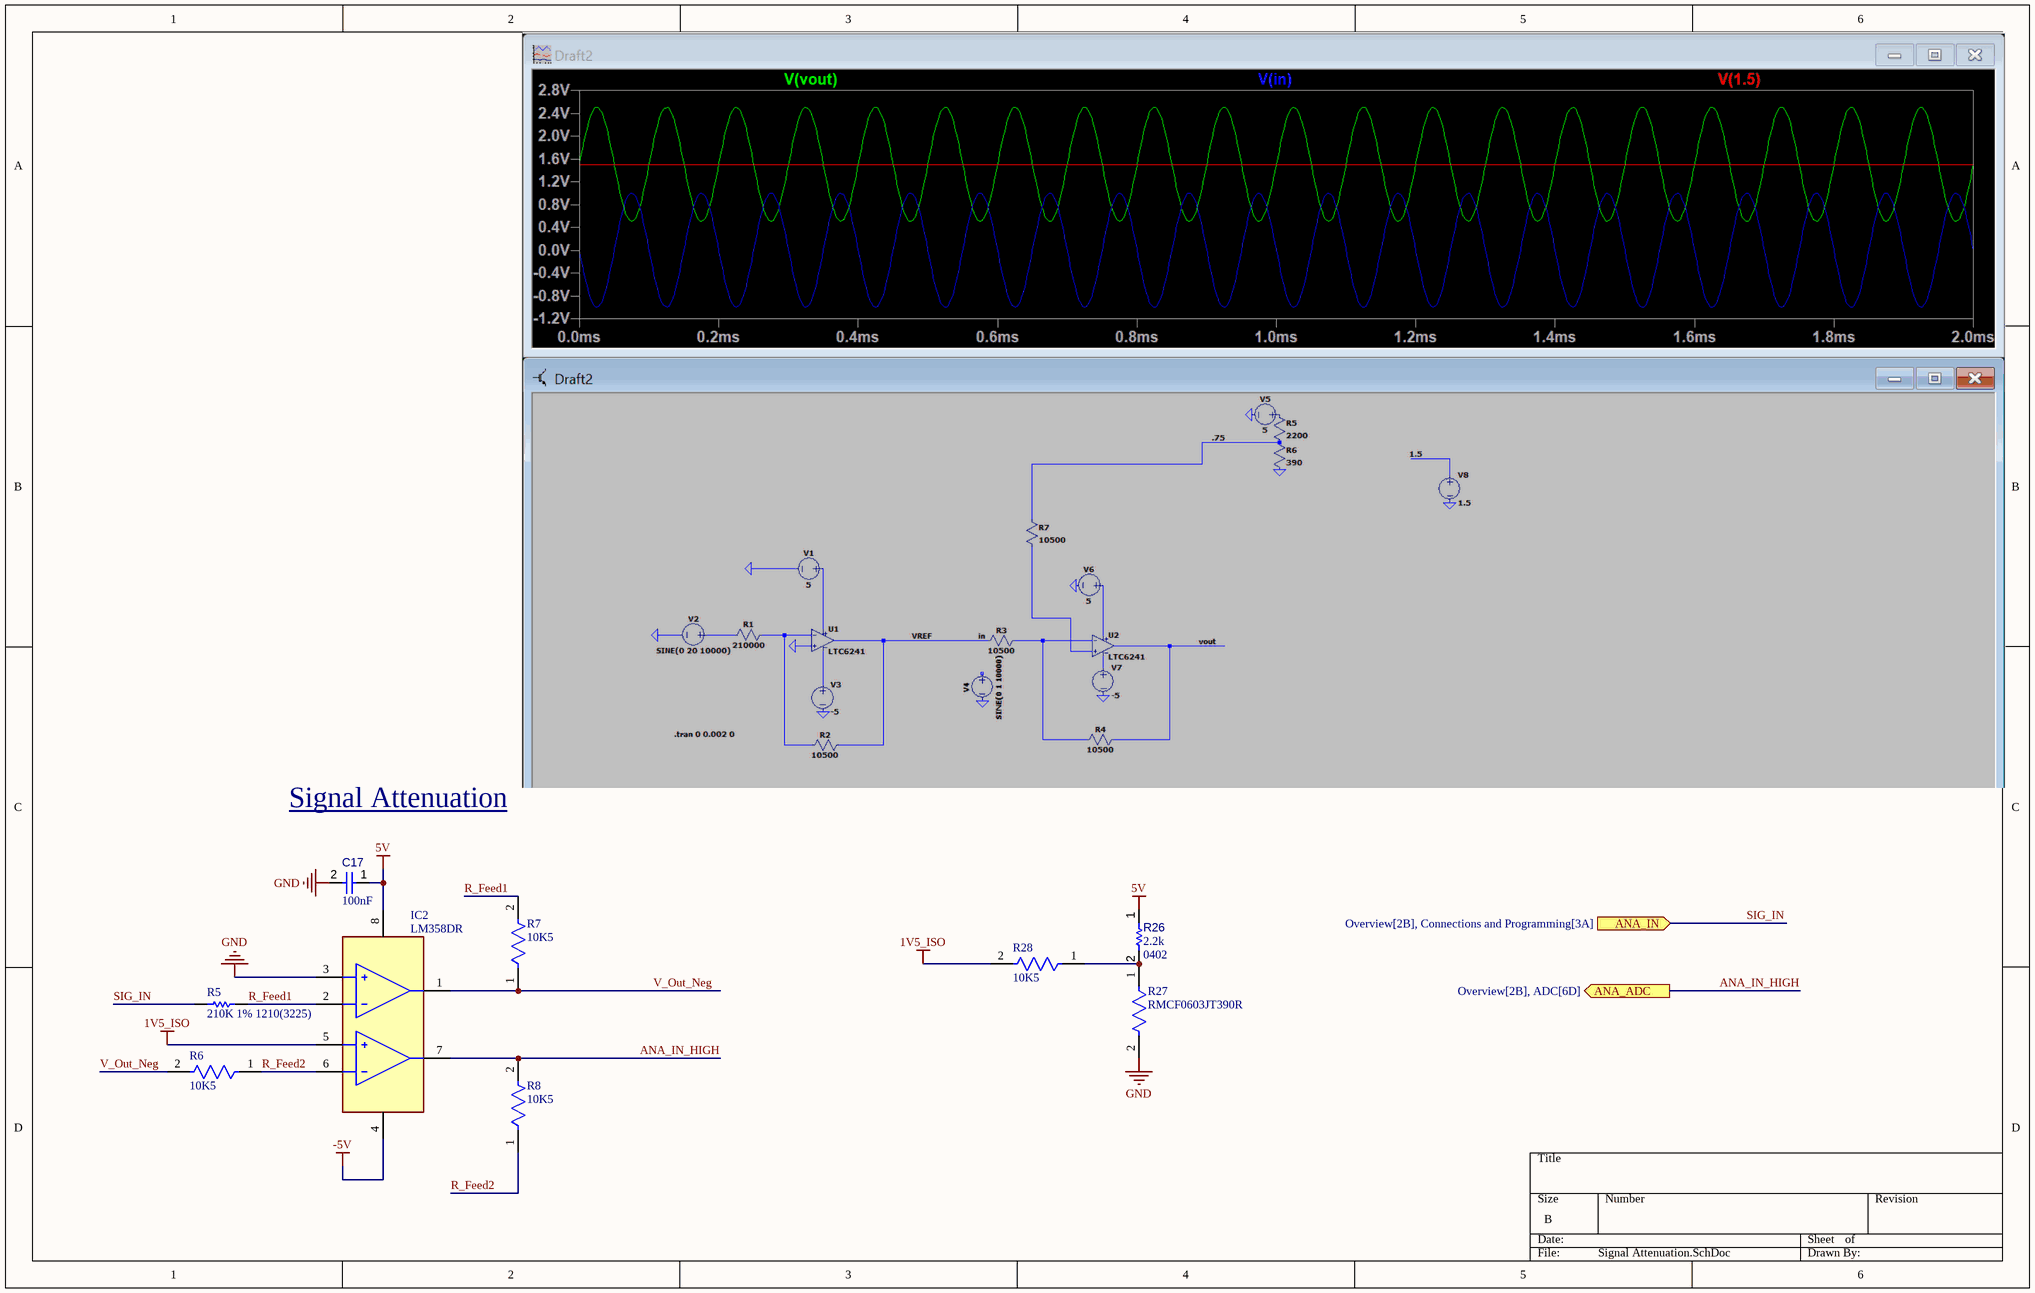
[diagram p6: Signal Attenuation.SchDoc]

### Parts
C17  value 100nF  [CAPC0402(1005)60_L]  (hidden comment: Capacitor 100nF +/-20% 10V 0402)
IC2  LM358DR  [SOIC127P600X175-8N]
R5  210K 1% 1210(3225)  [RESC1210(3225)_L]
R6  10K5  [FP-CRCW0805-HPe3-IPC_B]
R7  10K5  [FP-CRCW0805-HPe3-IPC_B]
R8  10K5  [FP-CRCW0805-HPe3-IPC_B]
R26  value 2.2k  Case/Package: 0402  [RESC0402(1005)_L]  (hidden comment: Resistor 2K2  +/-5 % 0402 63 mW)
R27  RMCF0603JT390R  [FP-RMCF0603-IPC_A]
R28  10K5  [FP-CRCW0805-HPe3-IPC_B]

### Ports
ANA_ADC (out, see Overview[2B], ADC[6D]), ANA_IN (in, see Overview[2B], Connections and Programming[3A])

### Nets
1V5_ISO: IC2.5(IN2+) R28.2
5V: C17.1 IC2.8(V+) R26.1  [project net 5V_BUS]
-5V: IC2.4(V-)
GND: C17.2 IC2.3(IN1+) R27.2
ANA_IN_HIGH: IC2.7(OUT2) R8.2 ; port ANA_ADC
R_Feed1: IC2.2(IN1-) R5.2 R7.2
R_Feed2: IC2.6(IN2-) R6.1 R8.1
SIG_IN: R5.1 ; port ANA_IN  [project net ANA_IN]
V_Out_Neg: IC2.1(OUT1) R6.2 R7.1
NetR26_2: R26.2 R27.1 R28.1

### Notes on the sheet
- Signal Attenuation

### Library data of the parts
C17 = CMP-001-00061-3: as C19 on sheet micro
IC2 = LM358DR: Integrated Circuit; Manufacturer_Name: Texas Instruments
R5 = CMP-1015-00770-1: 210K 0.5W 1% 1210 (3225 Metric)  SMD; Case-EIA: 1210; Value: 210000.00 Ohm; Case-Metric: 3225
R6-R8 R28 = CMP-02407-008889-1: RES Thick Film, 10.5kΩ, 1%, 0.5W, 100ppm/°C, 0805; Max Power Dissipation: 333mW; Resistance: 10.5kR
R26 = CMP-009-00166-3: Chip Resistor, 2,2 kOhms, +/-5 %, 63 mW, -55 to 155 degC, 0402; Tolerance: 5%; Power: 63mW
R27 = CMP-26527-007258-1: 390Ω ±5% 0.1W 0603 Thick Film Chip Resistor AEC-Q200 compliant; Max Power Dissipation: 100mW; Temperature Coefficient: 200ppm/°C; Resistance: 390R

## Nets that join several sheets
3V3: micro (35 pins), ADC (8 pins), LogicAnalyzer (C23.2 R4.2 U4.2 U4.10), Power (C40.2 U5.3)
5V_BUS: Connections and Programming (J9.02), micro (R12.1), Power (C39.2 U2.8 U5.1), Signal Attenuation (C17.1 IC2.8 R26.1)
-5V: Power (C16.2 U2.5), Signal Attenuation (IC2.4)
GND: Connections and Programming (5 pins), micro (41 pins), ADC (18 pins), LogicAnalyzer (8 pins), Power (7 pins), Signal Attenuation (C17.2 IC2.3 R27.2)
ADC_CLK: micro (IC1.4), ADC (U1.9)
ANA_IN: Connections and Programming (J8.1), Signal Attenuation (R5.1)
ANA_IN_HIGH: ADC (R9.1), Signal Attenuation (IC2.7 R8.2)
D0: micro (IC1.10), ADC (U1.16)
D1: micro (IC1.11), ADC (U1.17)
D2: micro (IC1.12), ADC (U1.18)
D3: micro (IC1.13), ADC (U1.19)
D4: micro (IC1.14), ADC (U1.22)
D5: micro (IC1.15), ADC (U1.23)
D6: micro (IC1.18), ADC (U1.24)
D7: micro (IC1.19), ADC (U1.25)
D8: micro (IC1.20), ADC (U1.26)
D9: micro (IC1.21), ADC (U1.27)
DIN_1: Connections and Programming (J10.1), LogicAnalyzer (D1.1 U4.20)
DIN_2: Connections and Programming (J10.2), LogicAnalyzer (D1.3 U4.18)
DIN_3: Connections and Programming (J10.3), LogicAnalyzer (D1.4 U4.17)
DIN_4: Connections and Programming (J10.4), LogicAnalyzer (D1.6 U4.16)
DIN_5: Connections and Programming (J10.5), LogicAnalyzer (D2.1 U4.15)
DIN_6: Connections and Programming (J10.6), LogicAnalyzer (D2.3 U4.14)
DIN_7: Connections and Programming (J10.7), LogicAnalyzer (D2.4 U4.13)
DIN_8: Connections and Programming (J10.8), LogicAnalyzer (D2.6 U4.12)
I2C1_SCL: Connections and Programming (J9.09), micro (IC1.139)
I2C1_SDA: Connections and Programming (J9.10), micro (IC1.140)
Log_01: micro (IC1.56), LogicAnalyzer (U4.1)
Log_02: micro (IC1.57), LogicAnalyzer (U4.3)
Log_03: micro (IC1.87), LogicAnalyzer (U4.4)
Log_04: micro (IC1.88), LogicAnalyzer (U4.5)
Log_05: micro (IC1.89), LogicAnalyzer (U4.6)
Log_06: micro (IC1.90), LogicAnalyzer (U4.7)
Log_07: micro (IC1.91), LogicAnalyzer (U4.8)
Log_08: micro (IC1.92), LogicAnalyzer (U4.9)
SPI_MISO: Connections and Programming (J9.05), micro (IC1.42)
SPI_MOSI: Connections and Programming (J9.04), micro (IC1.43)
SPI_SCK: Connections and Programming (J9.06), micro (IC1.41)
VREF: Connections and Programming (J10.9), LogicAnalyzer (C24.2 U4.19)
